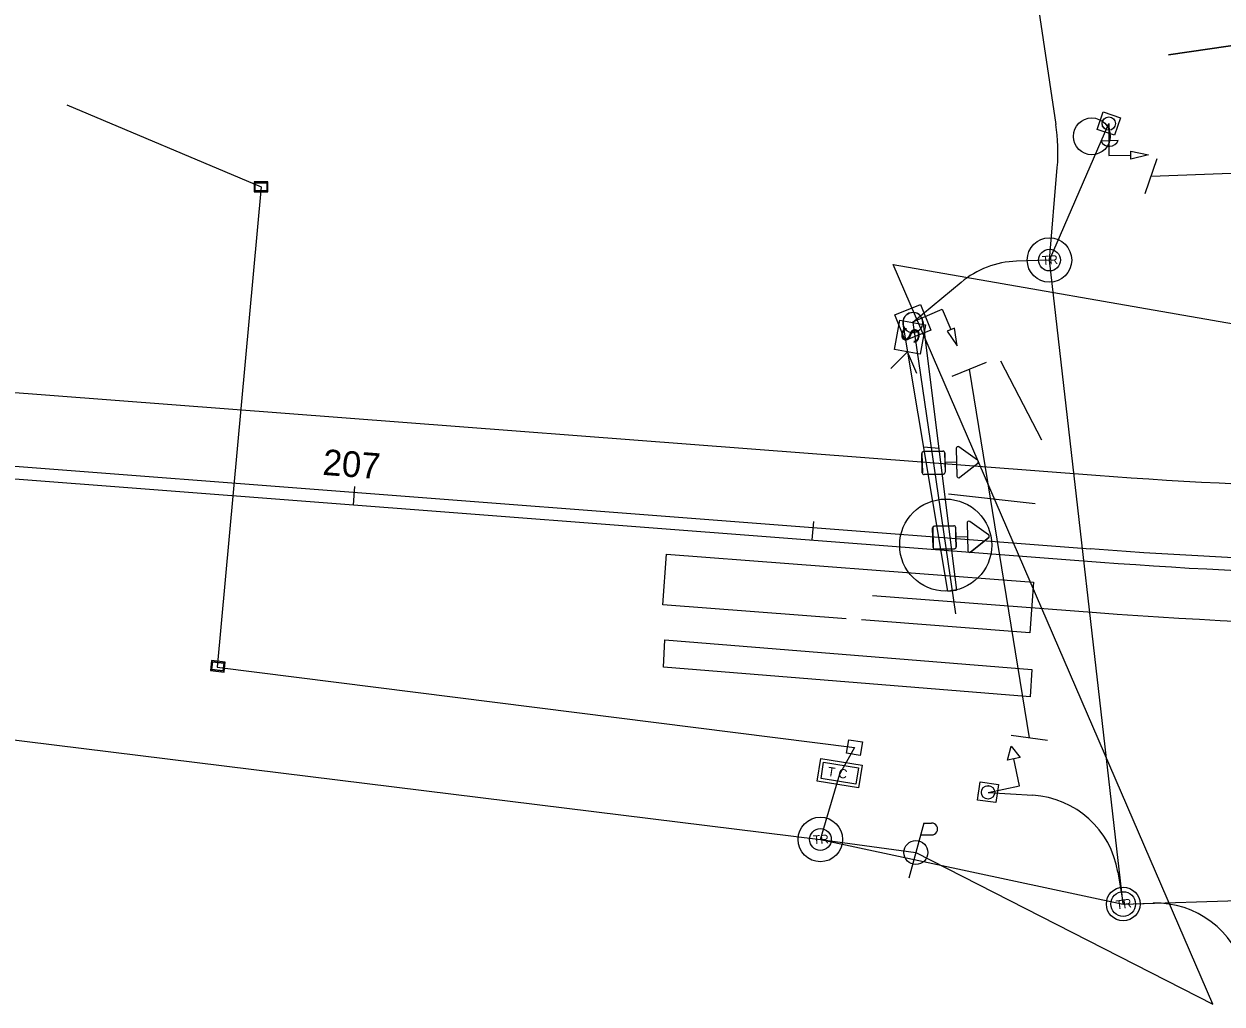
# Model space of a CAD drawing. Extents: x 1827063 to 1831280, y 711192 to 712800.
# Drawn here: x 1828503.6 to 1828633.8, y 711527.3 to 711633.8 of the extents above; entities that cross this region are included whole.
import ezdxf

# ---------------------------------------------------------------- set-up
doc = ezdxf.new("R2010")
doc.units = 0
for name, color, linetype in [('BR_P_Beam_Object', 7, 'Continuous'), ('BR_P_Sub_Centerline', 7, 'Continuous'), ('BR_X_Sub_Object', 7, 'Continuous'), ('Default', 7, 'Continuous'), ('DR_P_Cells', 7, 'Continuous'), ('DR_P_Storm_Sewer', 7, 'Continuous'), ('PM_P_Crosswalk', 7, 'Continuous'), ('PV_P_Walk', 7, 'Continuous'), ('PV_X_EOP', 7, 'Continuous'), ('SC_Shading1', 7, 'Continuous'), ('SG_P_Foundation', 7, 'Continuous'), ('SG_P_Interconnect_Cable', 7, 'Continuous'), ('SG_P_Wiring', 7, 'Continuous'), ('SG_X_Interconnect_Cable', 7, 'Continuous'), ('SG_X_Messenger_Wire', 7, 'Continuous'), ('TX_P_20', 7, 'Continuous'), ('UT_P_Water', 7, 'Continuous'), ('UT_P_Water_Cells', 7, 'Continuous'), ('UT_X_Electric_Cells', 7, 'Continuous')]:
    doc.layers.add(name, color=color, linetype=linetype)

# ---------------------------------------------------------------- blocks, each defined once
blk = doc.blocks.new('SPOLE_1')
at = {"layer": 'Default'}
blk.add_circle((0, 0), 0.0138, dxfattribs=at)
blk = doc.blocks.new('A$C258B21FD')
at = {"layer": 'Default'}
for p, q in [((1.209, 0.609), (1.307, 1.09)), ((1.307, 1.09), (1.431, 0.61)), ((1.431, 0.61), (1.209, 0.609))]:
    blk.add_line(p, q, dxfattribs=at)
for points in [[(1.431, 0.61), (1.209, 0.609), (1.307, 1.09), (1.431, 0.61)], [(0.442, 0), (1.32, -0.003), (1.32, 0.609)]]:
    blk.add_lwpolyline(points, dxfattribs=at)
blk = doc.blocks.new('Sighead')
at = {"layer": 'Default'}
for p, q in [((-0.03, 0.975), (-0.335, 0.569)), ((0.335, 0.569), (0.03, 0.975)), ((-0.305, 0.508), (0.305, 0.508)), ((0, 0.508), (0, 0.254)), ((-0.254, -0.216), (-0.254, 0.216)), ((-0.216, 0.254), (0.216, 0.254)), ((0.254, 0.216), (0.254, -0.216)), ((0.216, -0.254), (-0.216, -0.254))]:
    blk.add_line(p, q, dxfattribs=at)
for centre, start, end in [((0, 0.953), 36.8699, 143.1301), ((-0.305, 0.546), 143.1301, 270), ((0.305, 0.546), 270, 36.8699), ((-0.216, 0.216), 90, 180), ((0.216, 0.216), 0, 90), ((-0.216, -0.216), 180, 270), ((0.216, -0.216), 270, 0)]:
    blk.add_arc(centre, 0.0381, start, end, dxfattribs=at)
blk = doc.blocks.new('A$C70A22DE5')
at = {"layer": 'Default'}
for p, q in [((0, 0), (0.476, 0)), ((0.476, 0.236), (0.476, -0.236))]:
    blk.add_line(p, q, dxfattribs=at)
blk.add_arc((0.369, 0), 0.259, 294.3601, 65.6399, dxfattribs=at)

msp = doc.modelspace()

# ---------------------------------------------------------------- linework, layer by layer
at = {"layer": 'BR_P_Beam_Object'}
for p, q in [((1828604, 711572.16), (1828599.14, 711601.18)), ((1828601.3, 711601.49), (1828604.96, 711572.28)), ((1828604.96, 711572.28), (1828604, 711572.16))]:
    msp.add_line(p, q, dxfattribs=at)
msp.add_arc((1828600.22, 711601.34), 1.09, 8.341, 188.341, dxfattribs=at)
at = {"layer": 'BR_P_Sub_Centerline'}
for centre, radius in [((1828615.05, 711608.14), 2.42), ((1828615.05, 711608.14), 1.18), ((1828623.06, 711538.18), 1.83), ((1828623.06, 711538.18), 1.83), ((1828623.06, 711538.18), 1.83), ((1828623.06, 711538.18), 1.34), ((1828623.06, 711538.18), 1.34), ((1828623.06, 711538.18), 1.34)]:
    msp.add_circle(centre, radius, dxfattribs=at)
at = {"layer": 'BR_X_Sub_Object'}
for p, q in [((1828597.82, 711596.34), (1828599.6, 711598.16)), ((1828600.62, 711595.83), (1828599.6, 711598.16)), ((1828573.01, 711570.7), (1828573.43, 711576.18)), ((1828573.43, 711576.18), (1828613.32, 711573.13)), ((1828613.32, 711573.13), (1828612.9, 711567.64)), ((1828592.95, 711569.17), (1828573.01, 711570.7)), ((1828612.9, 711567.64), (1828594.62, 711569.04)), ((1828573.08, 711563.9), (1828573.26, 711566.89)), ((1828573.26, 711566.89), (1828613.13, 711563.67)), ((1828612.95, 711560.68), (1828573.08, 711563.9)), ((1828613.13, 711563.67), (1828612.95, 711560.68))]:
    msp.add_line(p, q, dxfattribs=at)
msp.add_lwpolyline([(1828598.21, 711598.41), (1828598.79, 711601.61), (1828601.59, 711601.1), (1828601, 711597.9)], close=True, dxfattribs=at)
at = {"layer": 'DR_P_Cells'}
for points in [[(1828620.87, 711624.24), (1828622.77, 711623.6), (1828622.12, 711621.7), (1828620.23, 711622.34)], [(1828607.24, 711549.46), (1828607.52, 711551.44), (1828609.5, 711551.17), (1828609.22, 711549.19)]]:
    msp.add_lwpolyline(points, close=True, dxfattribs=at)
for centre in [(1828621.5, 711622.97), (1828608.37, 711550.31)]:
    msp.add_circle(centre, 0.727, dxfattribs=at)
at = {"layer": 'DR_P_Storm_Sewer'}
for p, q in [((1828394.91, 711592.6), (1828620.59, 711575.33)), ((1828539.41, 711581.54), (1828539.56, 711583.54)), ((1828589.26, 711577.73), (1828589.42, 711579.72))]:
    msp.add_line(p, q, dxfattribs=at)
msp.add_arc((1828658.72, 712073.54), 499.67, 265.6226, 279.7988, dxfattribs=at)
at = {"layer": 'PM_P_Crosswalk'}
for p, q in [((1828641.01, 711632.32), (1828628, 711630.45)), ((1828628, 711630.45), (1828641.01, 711632.32)), ((1828394.43, 711602.04), (1828620.1, 711584.76)), ((1828393.82, 711594.06), (1828619.49, 711576.78)), ((1828601.38, 711587.83), (1828603.03, 711587.7))]:
    msp.add_line(p, q, dxfattribs=at)
for radius in [495.67, 503.67]:
    msp.add_arc((1828657.93, 712078.99), radius, 265.6226, 279.7988, dxfattribs=at)
at = {"layer": 'PV_P_Walk'}
for p, q in [((1828600.19, 711601.35), (1828604.85, 711569.69)), ((1828609.72, 711597.2), (1828614.19, 711588.62)), ((1828603.48, 711587.39), (1828601.35, 711587.33)), ((1828607.24, 711586.39), (1828605.2, 711587.84)), ((1828601.17, 711587.14), (1828601.23, 711585.02)), ((1828605.29, 711584.54), (1828607.25, 711586.09)), ((1828601.42, 711584.83), (1828603.54, 711584.89)), ((1828604.09, 711582.74), (1828613.51, 711581.68)), ((1828608.43, 711578.27), (1828606.39, 711579.72)), ((1828602.36, 711579.03), (1828602.41, 711576.9)), ((1828604.66, 711579.28), (1828602.54, 711579.22)), ((1828606.48, 711576.42), (1828608.44, 711577.98)), ((1828602.61, 711576.72), (1828604.73, 711576.78)), ((1828604, 711572.16), (1828604.96, 711572.28))]:
    msp.add_line(p, q, dxfattribs=at)
for points in [[(1828604.91, 711587.68), (1828604.95, 711586.18), (1828604.99, 711584.68)], [(1828603.73, 711585.08), (1828603.7, 711586.14), (1828603.67, 711587.21)], [(1828606.09, 711579.56), (1828606.13, 711578.06), (1828606.17, 711576.56)], [(1828604.91, 711576.97), (1828604.88, 711578.03), (1828604.86, 711579.09)]]:
    msp.add_lwpolyline(points, dxfattribs=at)
for centre, radius in [((1828619.65, 711621.58), 2), ((1828603.77, 711577.17), 5)]:
    msp.add_circle(centre, radius, dxfattribs=at)
for centre, start, end in [((1828601.36, 711587.15), 91.5231, 181.5231), ((1828603.48, 711587.2), 1.5231, 91.5231), ((1828605.1, 711587.68), 54.6532, 181.5231), ((1828607.13, 711586.24), 308.393, 54.6532), ((1828601.41, 711585.02), 181.5231, 271.5231), ((1828603.54, 711585.08), 271.5231, 1.5231), ((1828605.18, 711584.68), 181.5231, 308.393), ((1828606.28, 711579.57), 54.6532, 181.5231), ((1828602.54, 711579.03), 91.5231, 181.5231), ((1828604.67, 711579.09), 1.5231, 91.5231), ((1828608.32, 711578.12), 308.393, 54.6532), ((1828602.6, 711576.91), 181.5231, 271.5231), ((1828604.72, 711576.96), 271.5231, 1.5231), ((1828606.36, 711576.57), 181.5231, 308.393)]:
    msp.add_arc(centre, 0.187, start, end, dxfattribs=at)
at = {"layer": 'PV_X_EOP'}
for p, q in [((1828625.46, 711615.38), (1828626.76, 711619.17)), ((1828626.11, 711617.27), (1828688.04, 711619.59)), ((1828604.49, 711595.51), (1828608.19, 711597.03)), ((1828612.86, 711556.25), (1828606.34, 711596.27)), ((1828595.82, 711571.71), (1828620.17, 711569.84)), ((1828610.88, 711556.53), (1828614.85, 711555.98))]:
    msp.add_line(p, q, dxfattribs=at)
msp.add_arc((1828658.72, 712073.54), 505.17, 265.6226, 273.77, dxfattribs=at)
at = {"layer": 'SC_Shading1'}
for points in [[(1828594.48, 711554.32), (1828593, 711554.55), (1828593.23, 711556.03), (1828594.72, 711555.8)], [(1828590.22, 711551.81), (1828590.5, 711553.58), (1828594.3, 711552.98), (1828594.02, 711551.21)]]:
    msp.add_lwpolyline(points, close=True, dxfattribs=at)
msp.add_lwpolyline([(1828589.81, 711551.52), (1828590.2, 711553.98), (1828594.7, 711553.27), (1828594.31, 711550.8), (1828589.81, 711551.52)], dxfattribs=at)
at = {"layer": 'SG_P_Foundation'}
for p, q in [((1828598.24, 711602.18), (1828601.02, 711603.31)), ((1828601.02, 711603.31), (1828602.15, 711600.53)), ((1828599.37, 711599.4), (1828598.24, 711602.18)), ((1828602.15, 711600.53), (1828599.37, 711599.4))]:
    msp.add_line(p, q, dxfattribs=at)
for start, end in [(112.074, 292.074), (292.074, 112.074)]:
    msp.add_arc((1828600.19, 711601.35), 1.09, start, end, dxfattribs=at)
at = {"layer": 'SG_P_Interconnect_Cable'}
for p, q in [((1828582.9, 711839.83), (1828615.75, 711622.86)), ((1828615.05, 711608.14), (1828615.9, 711618.18)), ((1828623.06, 711538.18), (1828615.05, 711608.14)), ((1828590.15, 711545.19), (1828623.06, 711538.18)), ((1828623.06, 711538.18), (1828717.38, 711540.98))]:
    msp.add_line(p, q, dxfattribs=at)
msp.add_arc((1828595.97, 711619.87), 20, 355.1607, 8.6101, dxfattribs=at)
msp.add_arc((1828595.97, 711619.87), 20, 355.1607, 8.6101, dxfattribs=at)
at = {"layer": 'SG_P_Wiring'}
for p, q in [((1828615.05, 711608.14), (1828621.5, 711622.97)), ((1828615.05, 711608.14), (1828611.48, 711608.01)), ((1828605.45, 711605.71), (1828600.19, 711601.35)), ((1828593.86, 711555.18), (1828592.28, 711552.32)), ((1828590.15, 711545.19), (1828592.28, 711552.32)), ((1828608.37, 711550.31), (1828613.25, 711550)), ((1828622.49, 711541.66), (1828623.06, 711538.18))]:
    msp.add_line(p, q, dxfattribs=at)
for points in [[(1828508.26, 711624.99), (1828529.35, 711616.09)], [(1828529.35, 711616.09), (1828524.6, 711563.92)], [(1828524.6, 711563.92), (1828593.86, 711555.18)], [(1828623.06, 711538.18), (1828626.3, 711538.27)]]:
    msp.add_lwpolyline(points, dxfattribs=at)
for centre, start, end in [((1828611.83, 711598.02), 92.0423, 129.6713), ((1828612.62, 711540.02), 9.3998, 86.372), ((1828626.59, 711528.28), 14.2206, 91.6412)]:
    msp.add_arc(centre, 10, start, end, dxfattribs=at)
at = {"layer": 'SG_X_Interconnect_Cable'}
for p, q in [((1828464.14, 711560.77), (1828590.15, 711545.19)), ((1828590.15, 711545.19), (1828600.53, 711543.77))]:
    msp.add_line(p, q, dxfattribs=at)
at = {"layer": 'SG_X_Messenger_Wire'}
for p, q in [((1828632.81, 711527.31), (1828598.06, 711607.67)), ((1828598.06, 711607.67), (1828715.04, 711587.28)), ((1828600.53, 711543.77), (1828632.81, 711527.31))]:
    msp.add_line(p, q, dxfattribs=at)
at = {"layer": 'TX_P_20'}
for p, q in [((1828530.1, 711616.63), (1828528.6, 711616.63)), ((1828528.6, 711616.63), (1828528.6, 711615.55)), ((1828528.72, 711615.66), (1828528.72, 711616.52)), ((1828528.72, 711616.52), (1828529.99, 711616.52)), ((1828529.99, 711616.52), (1828529.99, 711615.66)), ((1828530.1, 711615.55), (1828530.1, 711616.63)), ((1828528.6, 711615.55), (1828530.1, 711615.55)), ((1828529.99, 711615.66), (1828528.72, 711615.66)), ((1828523.97, 711564.62), (1828523.85, 711563.55)), ((1828523.97, 711564.62), (1828523.85, 711563.55)), ((1828525.46, 711564.45), (1828523.97, 711564.62)), ((1828525.46, 711564.45), (1828523.97, 711564.62)), ((1828524.07, 711564.5), (1828523.97, 711563.64)), ((1828523.97, 711563.64), (1828524.07, 711564.5)), ((1828525.34, 711564.35), (1828524.07, 711564.5)), ((1828524.07, 711564.5), (1828525.34, 711564.35)), ((1828525.24, 711563.5), (1828525.34, 711564.35)), ((1828525.34, 711564.35), (1828525.24, 711563.5)), ((1828525.34, 711563.37), (1828525.46, 711564.45)), ((1828525.34, 711563.37), (1828525.46, 711564.45)), ((1828523.85, 711563.55), (1828525.34, 711563.37)), ((1828523.85, 711563.55), (1828525.34, 711563.37)), ((1828523.97, 711563.64), (1828525.24, 711563.5)), ((1828525.24, 711563.5), (1828523.97, 711563.64))]:
    msp.add_line(p, q, dxfattribs=at)
at = {"layer": 'UT_P_Water'}
msp.add_line((1828607.2, 711550.07), (1828607.2, 711550.07), dxfattribs=at)
msp.add_lwpolyline([(1828611.87, 711554.11), (1828610.5, 711553.82), (1828610.9, 711555.33)], close=True, dxfattribs=at)
msp.add_lwpolyline([(1828608.37, 711550.31), (1828611.8, 711551.03), (1828611.19, 711553.96)], dxfattribs=at)
at = {"layer": 'UT_P_Water_Cells'}
for radius in [2.42, 1.18]:
    msp.add_circle((1828590.15, 711545.19), radius, dxfattribs=at)
at = {"layer": 'UT_X_Electric_Cells'}
for p, q in [((1828601.39, 711546.97), (1828599.78, 711540.97)), ((1828601.39, 711546.97), (1828602.24, 711546.97)), ((1828601.04, 711545.69), (1828602.24, 711545.69))]:
    msp.add_line(p, q, dxfattribs=at)
msp.add_circle((1828600.53, 711543.77), 1.3, dxfattribs=at)
msp.add_arc((1828602.25, 711546.33), 0.638, 268.8767, 91.1233, dxfattribs=at)

# ---------------------------------------------------------------- block references
at = {"layer": 'BR_X_Sub_Object', "xscale": 3.9417244, "yscale": 3.941724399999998, "rotation": -87.30059105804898}
msp.add_blockref('A$C70A22DE5', (1828621.5, 711622.97), dxfattribs=at)
at = {"layer": 'DR_P_Cells'}
for p, xscale, yscale, rotation in [((1828621.5, 711622.97), 52.495541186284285, 52.49554118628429, -18.73149811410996), ((1828608.37, 711550.31), 52.49554118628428, 52.495541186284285, 82.06409893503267)]:
    msp.add_blockref('SPOLE_1', p, dxfattribs=dict(at, xscale=xscale, yscale=yscale, rotation=rotation))
at = {"layer": 'PV_P_Walk', "xscale": 4.921250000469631, "yscale": 4.92125000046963, "rotation": -88.47691639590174}
for p in [(1828602.45, 711586.11), (1828603.63, 711578)]:
    msp.add_blockref('Sighead', p, dxfattribs=at)
at = {"layer": 'UT_P_Water'}
for p, xscale, yscale, rotation in [((1828621.49, 711624.71), 3.937, 3.936999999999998, -89.83147011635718), ((1828598.61, 711600.73), 3.9370000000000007, -3.9370000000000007, 23.283133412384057)]:
    msp.add_blockref('A$C258B21FD', p, dxfattribs=dict(at, xscale=xscale, yscale=yscale, rotation=rotation))

# ---------------------------------------------------------------- texts
at = {"layer": 'BR_P_Sub_Centerline'}
for rotation, p in [(3.7551, (1828614.28, 711607.61)), (7.7982, (1828622.33, 711537.59))]:
    msp.add_text('TR', height=0.962, rotation=rotation, dxfattribs=at).set_placement(p)
at = {"layer": 'BR_X_Sub_Object'}
msp.add_text('S', height=1.95, rotation=79.5577, dxfattribs=at).set_placement((1828600.74, 711598.94))
at = {"layer": 'DR_P_Storm_Sewer'}
msp.add_text('207', height=2.8, rotation=355.6226, dxfattribs=at).set_placement((1828535.98, 711584.81))
at = {"layer": 'SC_Shading1'}
msp.add_text('T C', height=0.996, rotation=350.9985, dxfattribs=at).set_placement((1828590.87, 711552.11))
at = {"layer": 'UT_P_Water_Cells'}
msp.add_text('TR', height=0.962, rotation=3.7551, dxfattribs=at).set_placement((1828589.38, 711544.66))

doc.saveas('drawing.dxf')
